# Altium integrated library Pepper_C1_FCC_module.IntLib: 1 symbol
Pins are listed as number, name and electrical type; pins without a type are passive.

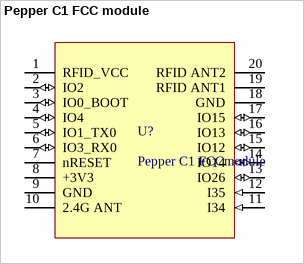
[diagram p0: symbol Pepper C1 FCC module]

## Pepper C1 FCC module
designator U?, comment Pepper C1 FCCmodule
RFID NFC Pepper C1 FCC module; Manufacturer: Eccel Technology Ltd; Manufacturer P/N: 000600
footprint Pepper_C1_FCC
pins: 1 RFID_VCC (power), 2 IO2 (io), 3 IO0_BOOT (io), 4 IO4 (io), 5 IO1_TX0 (io), 6 IO3_RX0 (io), 7 nRESET, 8 +3V3 (power), 9 GND (power), 10 2.4G ANT, 11 I34 (in), 12 I35 (in), 13 IO26 (io), 14 IO14 (io), 15 IO12 (io), 16 IO13 (io), 17 IO15 (io), 18 GND, 19 RFID ANT1, 20 RFID ANT2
